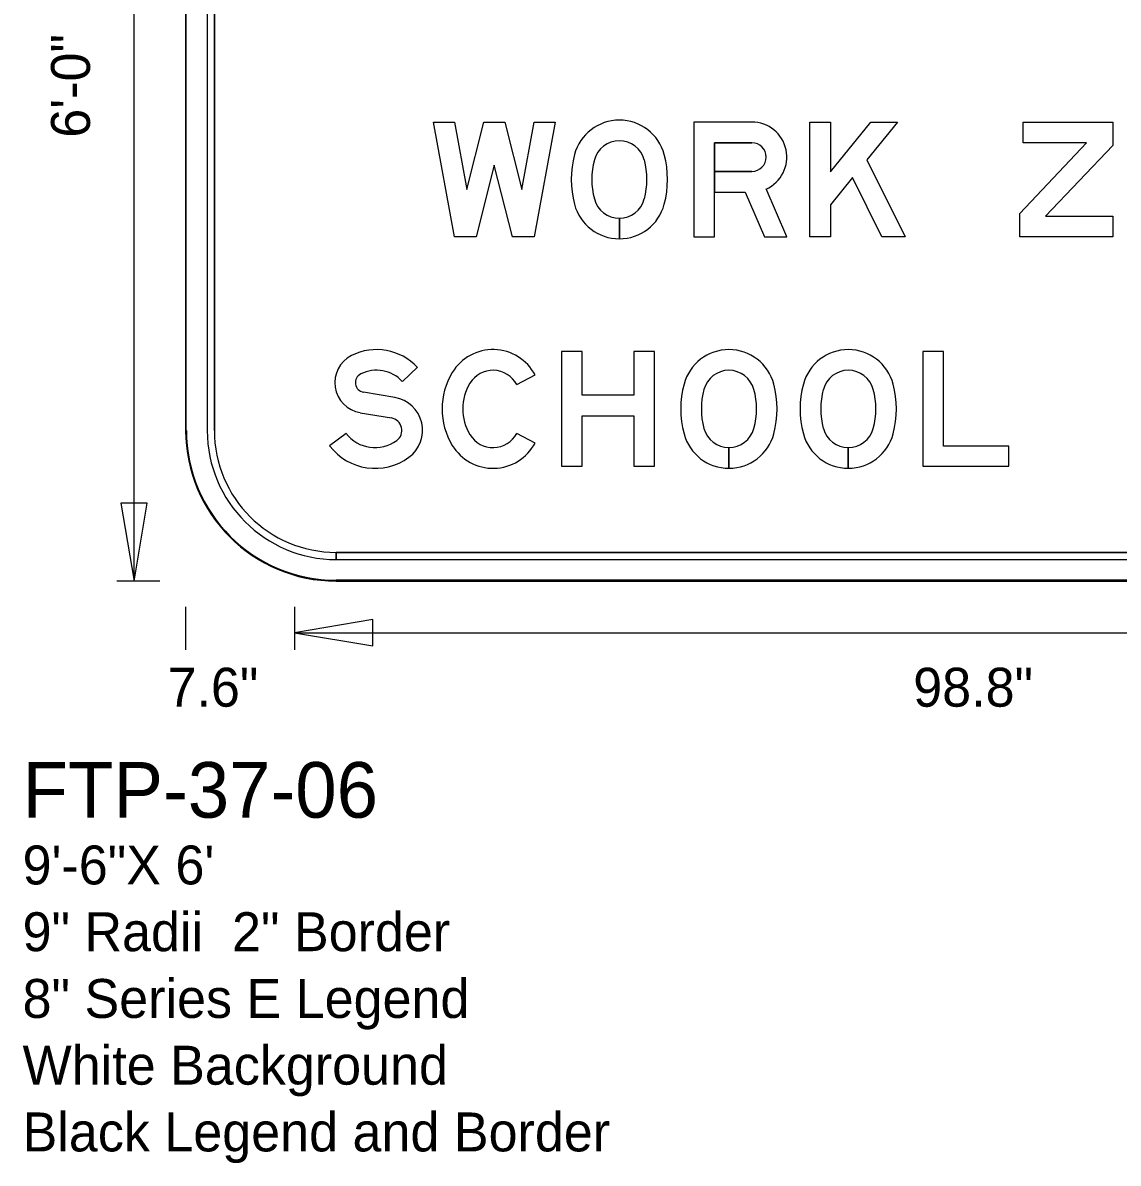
# Model space of a CAD drawing. Extents: x 0 to 770, y 0 to 495.
# Drawn here: x 6.3 to 104.8, y 1.3 to 103.8 of the extents above; entities that cross this region are included whole.
import ezdxf

# ---------------------------------------------------------------- set-up
doc = ezdxf.new("R2010")
doc.units = 0
for name, color, linetype in [('Dimension', 7, 'Continuous'), ('GSBWFill', 7, 'Continuous'), ('GSColorFill', 7, 'Continuous'), ('GSDims', 7, 'Continuous'), ('GSOutline', 7, 'Continuous'), ('TextStructures', 7, 'Continuous')]:
    doc.layers.add(name, color=color, linetype=linetype)

msp = doc.modelspace()

# ---------------------------------------------------------------- linework, layer by layer
at = {"layer": 'Dimension'}
for points in [[(16.3, 53.66), (17.49, 60.68), (15.11, 60.68)], [(30.74, 49.02), (37.76, 47.83), (37.76, 50.21)]]:
    msp.add_lwpolyline(points, close=True, dxfattribs=at)
at = {"layer": 'GSBWFill'}
for p, q in [((20.94, 132.96), (20.94, 67.2)), ((22.87, 132.96), (22.87, 67.2)), ((23.52, 67.2), (23.52, 132.96)), ((59.93, 84.43), (59.93, 86.29)), ((59.93, 86.29), (59.93, 84.43)), ((40.42, 71.61), (41.78, 72.88)), ((50.71, 71.33), (52.35, 72.21)), ((39.75, 70.16), (36.94, 70.63)), ((36.63, 68.8), (39.44, 68.33)), ((35.36, 66.94), (33.88, 65.81)), ((52.35, 66.07), (50.71, 66.94)), ((50.71, 66.94), (50.71, 66.94)), ((69.78, 63.8), (69.78, 65.66)), ((69.78, 65.66), (69.78, 63.8)), ((80.51, 63.8), (80.51, 65.66)), ((80.51, 65.66), (80.51, 63.8)), ((34.48, 55.6), (34.48, 56.24)), ((154.39, 56.24), (34.48, 56.24)), ((34.48, 56.24), (34.48, 55.6)), ((34.48, 55.6), (154.39, 55.6)), ((34.48, 53.66), (154.39, 53.66))]:
    msp.add_line(p, q, dxfattribs=at)
for points in [[(48.69, 91.06), (47.06, 84.61), (45.1, 84.61), (43.22, 94.92), (45.11, 94.92), (46.22, 88.85), (47.75, 94.92), (49.63, 94.92), (51.16, 88.85), (52.27, 94.92), (54.15, 94.92), (52.27, 84.61), (50.31, 84.61)], [(84.94, 94.92), (82.18, 91.52), (85.61, 84.61), (83.54, 84.61), (80.89, 89.94), (78.91, 87.5), (78.91, 84.61), (77.05, 84.61), (77.05, 94.92), (78.91, 94.92), (78.91, 90.44), (82.55, 94.92)], [(104.28, 86.47), (104.28, 84.61), (95.93, 84.61), (95.93, 86.72), (101.92, 93.07), (96.24, 93.07), (96.24, 94.92), (104.28, 94.92), (104.28, 92.81), (98.25, 86.47)], [(61.22, 70.37), (56.58, 70.37), (56.58, 74.29), (54.72, 74.29), (54.72, 63.98), (56.58, 63.98), (56.58, 68.52), (61.22, 68.52), (61.22, 63.98), (63.08, 63.98), (63.08, 74.29), (61.22, 74.29)], [(94.95, 63.98), (94.95, 65.78), (89.07, 65.78), (89.07, 74.29), (87.21, 74.29), (87.21, 63.98)]]:
    msp.add_lwpolyline(points, close=True, dxfattribs=at)
for points in [[(71.84, 94.92), (66.63, 94.92), (66.63, 84.61), (68.49, 84.61), (68.49, 93.07), (71.84, 93.07)], [(71.84, 90.49), (68.49, 90.49), (68.49, 88.63)], [(68.49, 88.63), (71.23, 88.63), (72.97, 84.61), (74.99, 84.61), (73.13, 88.91)]]:
    msp.add_lwpolyline(points, dxfattribs=at)
for centre, radius, start, end in [((59.93, 90.92), 4.18, 14.9618, 165.0382), ((59.93, 90.92), 2.32, 14.9618, 165.0382), ((64.26, 89.77), 8.66, 165.0382, 194.9618), ((64.26, 89.77), 6.81, 165.0382, 194.9618), ((55.6, 89.77), 6.81, 345.0382, 14.9618), ((55.6, 89.77), 8.66, 345.0382, 14.9618), ((59.93, 88.61), 4.18, 194.9618, 270), ((59.93, 88.61), 2.32, 194.9618, 270), ((59.93, 88.61), 2.32, 270.0127, 345.0382), ((59.93, 88.61), 4.18, 270.0071, 345.0382), ((37.08, 71.5), 2.73, 116.9123, 260.4087), ((38.11, 69.47), 5, 42.8759, 116.9123), ((69.78, 70.29), 4.18, 14.9618, 165.0382), ((80.51, 70.29), 4.18, 14.9618, 165.0382), ((37.08, 71.5), 0.877, 116.9123, 260.4087), ((38.11, 69.47), 3.15, 42.8759, 116.9123), ((69.78, 70.29), 2.32, 14.9618, 165.0382), ((80.51, 70.29), 2.32, 14.9618, 165.0382), ((74.11, 69.14), 8.66, 165.0382, 194.9618), ((74.11, 69.14), 6.81, 165.0382, 194.9618), ((65.45, 69.14), 6.81, 345.0382, 14.9618), ((65.45, 69.14), 8.66, 345.0382, 14.9618), ((84.84, 69.14), 8.66, 165.0382, 194.9618), ((84.84, 69.14), 6.81, 165.0382, 194.9618), ((76.18, 69.14), 6.81, 345.0382, 14.9618), ((76.18, 69.14), 8.66, 345.0382, 14.9618), ((39.25, 67.21), 2.99, 306.123, 80.4087), ((39.25, 67.21), 1.13, 306.123, 80.4087), ((34.48, 67.2), 13.54, 180, 270), ((34.48, 67.2), 11.6, 180, 270), ((34.48, 67.2), 10.96, 180, 270), ((37.97, 68.96), 3.3, 217.5895, 306.123), ((69.78, 67.98), 4.18, 194.9618, 270), ((69.78, 67.98), 2.32, 194.9618, 270), ((69.78, 67.98), 2.32, 270.0127, 345.0382), ((69.78, 67.98), 4.18, 270.0071, 345.0382), ((80.51, 67.98), 4.18, 194.9618, 270), ((80.51, 67.98), 2.32, 194.9618, 270), ((80.51, 67.98), 2.32, 270.0127, 345.0382), ((80.51, 67.98), 4.18, 270.0071, 345.0382), ((37.97, 68.96), 5.16, 217.5895, 306.123)]:
    msp.add_arc(centre, radius, start, end, dxfattribs=at)
for centre, major_axis, start_param, end_param in [((71.84, 91.78), (0, 3.15), 3.562504, 6.283185), ((71.84, 91.78), (0, 1.29), 3.141593, 6.283185), ((48.57, 70.19), (0, 4.28), 5.201543, 7.308565), ((50.31, 69.14), (0, 6.32), 1.025379, 2.116213), ((48.57, 70.19), (0, 2.42), 5.201543, 7.308565), ((50.31, 69.14), (0, 4.46), 1.025379, 2.116213), ((48.57, 68.08), (0, 2.42), 2.116213, 4.223235), ((48.57, 68.08), (0, 4.28), 2.116213, 4.223235)]:
    msp.add_ellipse(centre, major_axis=major_axis, ratio=0.999994, start_param=start_param, end_param=end_param, dxfattribs=at)
at = {"layer": 'GSColorFill'}
for p, q in [((20.94, 132.96), (20.94, 67.2)), ((20.94, 132.96), (20.94, 67.2)), ((21, 67.2), (21, 132.96)), ((22.87, 132.96), (22.87, 67.2)), ((23.52, 67.2), (23.52, 132.96)), ((59.93, 84.43), (59.93, 86.29)), ((59.93, 86.29), (59.93, 84.43)), ((40.42, 71.61), (41.78, 72.88)), ((50.71, 71.33), (52.35, 72.21)), ((39.75, 70.16), (36.94, 70.63)), ((36.63, 68.8), (39.44, 68.33)), ((35.36, 66.94), (33.88, 65.81)), ((52.35, 66.07), (50.71, 66.94)), ((50.71, 66.94), (50.71, 66.94)), ((69.78, 63.8), (69.78, 65.66)), ((69.78, 65.66), (69.78, 63.8)), ((80.51, 63.8), (80.51, 65.66)), ((80.51, 65.66), (80.51, 63.8)), ((34.48, 55.6), (34.48, 56.24)), ((154.39, 56.24), (34.48, 56.24)), ((34.48, 56.24), (34.48, 55.6)), ((34.48, 55.6), (154.39, 55.6)), ((34.48, 53.66), (34.48, 53.73)), ((154.39, 53.73), (34.48, 53.73)), ((34.48, 53.73), (34.48, 53.66)), ((34.48, 53.66), (154.39, 53.66)), ((34.48, 53.66), (154.39, 53.66))]:
    msp.add_line(p, q, dxfattribs=at)
for points in [[(48.69, 91.06), (47.06, 84.61), (45.1, 84.61), (43.22, 94.92), (45.11, 94.92), (46.22, 88.85), (47.75, 94.92), (49.63, 94.92), (51.16, 88.85), (52.27, 94.92), (54.15, 94.92), (52.27, 84.61), (50.31, 84.61)], [(84.94, 94.92), (82.18, 91.52), (85.61, 84.61), (83.54, 84.61), (80.89, 89.94), (78.91, 87.5), (78.91, 84.61), (77.05, 84.61), (77.05, 94.92), (78.91, 94.92), (78.91, 90.44), (82.55, 94.92)], [(104.28, 86.47), (104.28, 84.61), (95.93, 84.61), (95.93, 86.72), (101.92, 93.07), (96.24, 93.07), (96.24, 94.92), (104.28, 94.92), (104.28, 92.81), (98.25, 86.47)], [(61.22, 70.37), (56.58, 70.37), (56.58, 74.29), (54.72, 74.29), (54.72, 63.98), (56.58, 63.98), (56.58, 68.52), (61.22, 68.52), (61.22, 63.98), (63.08, 63.98), (63.08, 74.29), (61.22, 74.29)], [(94.95, 63.98), (94.95, 65.78), (89.07, 65.78), (89.07, 74.29), (87.21, 74.29), (87.21, 63.98)]]:
    msp.add_lwpolyline(points, close=True, dxfattribs=at)
for points in [[(71.84, 94.92), (66.63, 94.92), (66.63, 84.61), (68.49, 84.61), (68.49, 93.07), (71.84, 93.07)], [(71.84, 90.49), (68.49, 90.49), (68.49, 88.63)], [(68.49, 88.63), (71.23, 88.63), (72.97, 84.61), (74.99, 84.61), (73.13, 88.91)]]:
    msp.add_lwpolyline(points, dxfattribs=at)
for centre, radius, start, end in [((59.93, 90.92), 4.18, 14.9618, 165.0382), ((59.93, 90.92), 2.32, 14.9618, 165.0382), ((64.26, 89.77), 8.66, 165.0382, 194.9618), ((64.26, 89.77), 6.81, 165.0382, 194.9618), ((55.6, 89.77), 6.81, 345.0382, 14.9618), ((55.6, 89.77), 8.66, 345.0382, 14.9618), ((59.93, 88.61), 4.18, 194.9618, 270), ((59.93, 88.61), 2.32, 194.9618, 270), ((59.93, 88.61), 2.32, 270.0127, 345.0382), ((59.93, 88.61), 4.18, 270.0071, 345.0382), ((37.08, 71.5), 2.73, 116.9123, 260.4087), ((38.11, 69.47), 5, 42.8759, 116.9123), ((69.78, 70.29), 4.18, 14.9618, 165.0382), ((80.51, 70.29), 4.18, 14.9618, 165.0382), ((37.08, 71.5), 0.877, 116.9123, 260.4087), ((38.11, 69.47), 3.15, 42.8759, 116.9123), ((69.78, 70.29), 2.32, 14.9618, 165.0382), ((80.51, 70.29), 2.32, 14.9618, 165.0382), ((74.11, 69.14), 8.66, 165.0382, 194.9618), ((74.11, 69.14), 6.81, 165.0382, 194.9618), ((65.45, 69.14), 6.81, 345.0382, 14.9618), ((65.45, 69.14), 8.66, 345.0382, 14.9618), ((84.84, 69.14), 8.66, 165.0382, 194.9618), ((84.84, 69.14), 6.81, 165.0382, 194.9618), ((76.18, 69.14), 6.81, 345.0382, 14.9618), ((76.18, 69.14), 8.66, 345.0382, 14.9618), ((39.25, 67.21), 2.99, 306.123, 80.4087), ((39.25, 67.21), 1.13, 306.123, 80.4087), ((34.48, 67.2), 13.54, 180, 270), ((34.48, 67.2), 13.54, 180, 270), ((34.48, 67.2), 13.47, 180, 270), ((34.48, 67.2), 11.6, 180, 270), ((34.48, 67.2), 10.96, 180, 270), ((37.97, 68.96), 3.3, 217.5895, 306.123), ((69.78, 67.98), 4.18, 194.9618, 270), ((69.78, 67.98), 2.32, 194.9618, 270), ((69.78, 67.98), 2.32, 270.0127, 345.0382), ((69.78, 67.98), 4.18, 270.0071, 345.0382), ((80.51, 67.98), 4.18, 194.9618, 270), ((80.51, 67.98), 2.32, 194.9618, 270), ((80.51, 67.98), 2.32, 270.0127, 345.0382), ((80.51, 67.98), 4.18, 270.0071, 345.0382), ((37.97, 68.96), 5.16, 217.5895, 306.123)]:
    msp.add_arc(centre, radius, start, end, dxfattribs=at)
for centre, major_axis, start_param, end_param in [((71.84, 91.78), (0, 3.15), 3.562504, 6.283185), ((71.84, 91.78), (0, 1.29), 3.141593, 6.283185), ((48.57, 70.19), (0, 4.28), 5.201543, 7.308565), ((50.31, 69.14), (0, 6.32), 1.025379, 2.116213), ((48.57, 70.19), (0, 2.42), 5.201543, 7.308565), ((50.31, 69.14), (0, 4.46), 1.025379, 2.116213), ((48.57, 68.08), (0, 2.42), 2.116213, 4.223235), ((48.57, 68.08), (0, 4.28), 2.116213, 4.223235)]:
    msp.add_ellipse(centre, major_axis=major_axis, ratio=0.999994, start_param=start_param, end_param=end_param, dxfattribs=at)
at = {"layer": 'GSDims'}
for p, q in [((16.3, 53.66), (16.3, 146.5)), ((18.62, 53.66), (14.75, 53.66)), ((20.94, 51.34), (20.94, 47.47)), ((30.74, 51.34), (30.74, 47.47)), ((30.74, 51.34), (30.74, 47.47)), ((30.74, 49.02), (158.13, 49.02))]:
    msp.add_line(p, q, dxfattribs=at)
at = {"layer": 'GSOutline'}
for p, q in [((20.94, 132.96), (20.94, 67.2)), ((22.87, 132.96), (22.87, 67.2)), ((23.52, 132.96), (23.52, 67.2)), ((68.49, 90.49), (71.84, 90.49)), ((40.42, 71.61), (41.78, 72.88)), ((50.71, 71.33), (52.35, 72.21)), ((39.75, 70.16), (36.94, 70.63)), ((36.63, 68.8), (39.44, 68.33)), ((35.36, 66.94), (33.88, 65.81)), ((52.35, 66.07), (50.71, 66.94)), ((50.71, 66.94), (50.71, 66.94)), ((34.48, 56.24), (154.39, 56.24)), ((34.48, 55.6), (154.39, 55.6)), ((34.48, 53.66), (154.39, 53.66))]:
    msp.add_line(p, q, dxfattribs=at)
for points in [[(48.69, 91.06), (47.06, 84.61), (45.1, 84.61), (43.22, 94.92), (45.11, 94.92), (46.22, 88.85), (47.75, 94.92), (49.63, 94.92), (51.16, 88.85), (52.27, 94.92), (54.15, 94.92), (52.27, 84.61), (50.31, 84.61)], [(84.94, 94.92), (82.18, 91.52), (85.61, 84.61), (83.54, 84.61), (80.89, 89.94), (78.91, 87.5), (78.91, 84.61), (77.05, 84.61), (77.05, 94.92), (78.91, 94.92), (78.91, 90.44), (82.55, 94.92)], [(104.28, 86.47), (104.28, 84.61), (95.93, 84.61), (95.93, 86.72), (101.92, 93.07), (96.24, 93.07), (96.24, 94.92), (104.28, 94.92), (104.28, 92.81), (98.25, 86.47)], [(61.22, 70.37), (56.58, 70.37), (56.58, 74.29), (54.72, 74.29), (54.72, 63.98), (56.58, 63.98), (56.58, 68.52), (61.22, 68.52), (61.22, 63.98), (63.08, 63.98), (63.08, 74.29), (61.22, 74.29)], [(94.95, 63.98), (94.95, 65.78), (89.07, 65.78), (89.07, 74.29), (87.21, 74.29), (87.21, 63.98)]]:
    msp.add_lwpolyline(points, close=True, dxfattribs=at)
for points in [[(71.84, 94.92), (66.63, 94.92), (66.63, 84.61), (68.49, 84.61), (68.49, 88.63), (71.23, 88.63)], [(71.84, 93.07), (68.49, 93.07), (68.49, 90.49)], [(71.23, 88.63), (72.97, 84.61), (74.99, 84.61), (73.13, 88.91)]]:
    msp.add_lwpolyline(points, dxfattribs=at)
for centre, radius, start, end in [((59.93, 90.92), 4.18, 14.9618, 165.0382), ((59.93, 90.92), 2.32, 14.9618, 165.0382), ((64.26, 89.77), 8.66, 165.0382, 194.9618), ((64.26, 89.77), 6.81, 165.0382, 194.9618), ((55.6, 89.77), 6.81, 345.0382, 14.9618), ((55.6, 89.77), 8.66, 345.0382, 14.9618), ((59.93, 88.61), 4.18, 194.9618, 345.0382), ((59.93, 88.61), 2.32, 194.9618, 345.0382), ((37.08, 71.5), 2.73, 116.9123, 260.4087), ((38.11, 69.47), 5, 42.8759, 116.9123), ((69.78, 70.29), 4.18, 14.9618, 165.0382), ((80.51, 70.29), 4.18, 14.9618, 165.0382), ((37.08, 71.5), 0.877, 116.9123, 260.4087), ((38.11, 69.47), 3.15, 42.8759, 116.9123), ((69.78, 70.29), 2.32, 14.9618, 165.0382), ((80.51, 70.29), 2.32, 14.9618, 165.0382), ((74.11, 69.14), 8.66, 165.0382, 194.9618), ((74.11, 69.14), 6.81, 165.0382, 194.9618), ((65.45, 69.14), 6.81, 345.0382, 14.9618), ((65.45, 69.14), 8.66, 345.0382, 14.9618), ((84.84, 69.14), 8.66, 165.0382, 194.9618), ((84.84, 69.14), 6.81, 165.0382, 194.9618), ((76.18, 69.14), 6.81, 345.0382, 14.9618), ((76.18, 69.14), 8.66, 345.0382, 14.9618), ((39.25, 67.21), 2.99, 306.123, 80.4087), ((39.25, 67.21), 1.13, 306.123, 80.4087), ((34.48, 67.2), 13.54, 180, 270), ((34.48, 67.2), 11.6, 180, 270), ((34.48, 67.2), 10.96, 180, 270), ((37.97, 68.96), 3.3, 217.5895, 306.123), ((69.78, 67.98), 4.18, 194.9618, 345.0382), ((69.78, 67.98), 2.32, 194.9618, 345.0382), ((80.51, 67.98), 4.18, 194.9618, 345.0382), ((80.51, 67.98), 2.32, 194.9618, 345.0382), ((37.97, 68.96), 5.16, 217.5895, 306.123)]:
    msp.add_arc(centre, radius, start, end, dxfattribs=at)
for centre, major_axis, start_param, end_param in [((71.84, 91.78), (0, 3.15), 3.562504, 6.283185), ((71.84, 91.78), (0, 1.29), 3.141593, 6.283185), ((48.57, 70.19), (0, 4.28), 5.201543, 7.308565), ((50.31, 69.14), (0, 6.32), 1.025379, 2.116213), ((48.57, 70.19), (0, 2.42), 5.201543, 7.308565), ((50.31, 69.14), (0, 4.46), 1.025379, 2.116213), ((48.57, 68.08), (0, 2.42), 2.116213, 4.223235), ((48.57, 68.08), (0, 4.28), 2.116213, 4.223235)]:
    msp.add_ellipse(centre, major_axis=major_axis, ratio=0.999994, start_param=start_param, end_param=end_param, dxfattribs=at)

# ---------------------------------------------------------------- texts
at = {"layer": 'TextStructures'}
msp.add_text('6\'-0"', height=3.5, rotation=90, dxfattribs=at).set_placement((12.34, 93.52))
for s, height, p in [('7.6"', 3.5, (19.31, 42.37)), ('98.8"', 3.5, (86.35, 42.37)), ('FTP-37-06', 5, (6.28, 32.39)), ('9\'-6"X 6\'', 3.5, (6.28, 26.39)), ('9" Radii  2" Border', 3.5, (6.28, 20.39)), ('8" Series E Legend', 3.5, (6.28, 14.39)), ('White Background', 3.5, (6.28, 8.39)), ('Black Legend and Border', 3.5, (6.28, 2.39))]:
    msp.add_text(s, height=height, dxfattribs=at).set_placement(p)

doc.saveas('drawing.dxf')
